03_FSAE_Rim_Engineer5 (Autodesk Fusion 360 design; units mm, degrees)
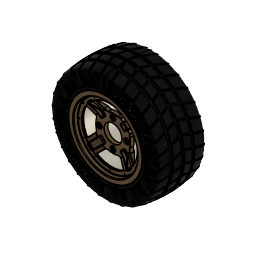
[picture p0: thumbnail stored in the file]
part number: 2026-07-27-09-56-27-671
part number: 2026-08-04-10-59-52-273
part number: 2026-08-04-10-59-52-284
part number: 2026-08-04-10-59-52-289
sketch "Sketch1" plane through (0, 0, 0) normal (1, 0, 0) x axis (0, 1, 0)
  line L1 (153.5, 0) -> (0, 0)
  line L2 (0, 119.5) -> (0, 104)
  line L3 (143.5, 124.5) -> (5, 124.5)
  line L4 (148.5, 134.75) -> (148.5, 129.5)
  line L5 (153.5, 138.25) -> (152, 138.25)
  line L6 (2.5, 119.5) -> (2.5, 104)
  line L7 (143.5, 122) -> (5, 122)
  line L8 (151, 134.75) -> (151, 129.5)
  line L9 (153.5, 135.75) -> (152, 135.75)
  line L10 (2.5, 104) -> (0, 104)
  line L11 (153.5, 135.75) -> (153.5, 138.25)
  arc A1 centre (152, 134.75) radius 3.5 clockwise from (148.5, 134.75) to (152, 138.25)
  arc A2 centre (143.5, 129.5) radius 5 clockwise from (148.5, 129.5) to (143.5, 124.5)
  arc A3 centre (5, 119.5) radius 5 clockwise from (0, 119.5) to (5, 124.5)
  arc A4 centre (5, 119.5) radius 2.5 clockwise from (2.5, 119.5) to (5, 122)
  arc A5 centre (143.5, 129.5) radius 7.5 clockwise from (151, 129.5) to (143.5, 122)
  arc A6 centre (152, 134.75) radius 1 clockwise from (151, 134.75) to (152, 135.75)
  point P1 (0, 0)
  point P2 (0, 0)
  point P4 (0, 104)
  point P3 (153.5, 0)
  point P7 (153.5, 138.25)
  point P6 (148.5, 124.5)
  point P5 (0, 124.5)
  coincident P1 P2
  horizontal L1
  perpendicular L1 L2
  perpendicular L2 L3
  perpendicular L3 L4
  perpendicular L4 L5
  vertical P1 P4
  vertical P3 P7
  tangent L4 A1
  tangent L5 A1
  coincident P6 L3
  coincident P6 L4
  tangent L3 A2
  tangent L4 A2
  coincident P5 L2
  coincident P5 L3
  tangent L2 A3
  tangent L3 A3
  equal A2 A3
  perpendicular L6 L10
  perpendicular L9 L11
  dimension "d1" distance P2 P3 = 153.5
  dimension "d2" = 208
  dimension "d3" = 249
  dimension "d4" = 276.5
  dimension "d5" distance P5 P6 = 148.5
  dimension "d6" radius A1 = 3.5
  dimension "d7" radius A2 = 5
  dimension "d8" = 2.5
revolve "Revolve1" sketch "Sketch1" AlongAngle 360 bodies "FSAE Rim Back"
sketch "Sketch2" plane through (0, 0, 0) normal (0, -1, 0) x axis (1, 0, 0)
  circle C1 centre (0, 0) radius 104
  circle C2 centre (0, 0) radius 119.5
  circle C3 centre (0, 0) radius 112
  circle C4 centre (0, 112) radius 2.15
  point P1 (0, 0)
  point P3 (0, 0)
  point P4 (0, 112)
  coincident P1 P3
  coincident C3 P4
  vertical P3 P4
  dimension "d10" diameter C3 = 224
  dimension "d11" diameter C4 = 4.3
extrude "Extrude1" cut sketch "Sketch2" profile of C4 to an object
circular_pattern "C-Pattern1" TotalAngle 360
canvas "Canvas1"
move "Move1"
sketch "Sketch4" plane through (0, 0, 0) normal (1, 0, 0) x axis (0, 1, 0)
  line L1 (14, 0) -> (0, 0)
  line L2 (14, 72.5) -> (14, 0)
  line L3 (-8, 102.5) -> (14, 72.5)
  line L4 (-8, 124.5) -> (-8, 102.5)
  line L5 (-23.5, 124.5) -> (-8, 124.5)
  line L6 (-23.5, 138) -> (-23.5, 124.5)
  line L7 (-28.25, 138) -> (-23.5, 138)
  line L8 (-28.25, 0) -> (-28.25, 138)
  line L9 (0, 0) -> (-28.25, 0)
  line L10 (-13, 118.1658) -> (-28.25, 119.5)
  line L11 (-13, 102.5) -> (-13, 118.1658)
  line L12 (0, 68.6338) -> (-13, 102.5)
  line L13 (0, 0) -> (0, 68.6338)
  point P1 (0, 0)
  point P2 (0, 0)
  point P11 (0, 0)
  point P12 (-28.25, 119.5)
  point P5 (-8, 102.5)
  point P14 (-13, 102.5)
  point P3 (14, 0)
  point P4 (14, 72.5)
  point P6 (-8, 124.5)
  point P8 (-23.5, 138)
  point P9 (-28.25, 138)
  coincident P1 P2
  horizontal L1
  perpendicular L1 L2
  perpendicular L1 L4
  perpendicular L4 L5
  perpendicular L5 L6
  perpendicular L6 L7
  coincident P1 P11
  collinear L1 L9
  perpendicular L8 L9
  coincident L8 P12
  parallel L8 L11
  vertical L13
  horizontal P5 P14
  dimension "d29" distance P2 P3 = 14
  dimension "d30" = 145
  dimension "d31" = 205
  dimension "d32" = 249
  dimension "d33" = 276
  dimension "d34" distance P4 P6 = 22
  dimension "d35" distance P6 P8 = 15.5
  dimension "d36" distance P8 P9 = 4.75
  dimension "d37" distance L4 L11 = 5
  dimension "d38" angle L12 L13 = 159
  dimension "d39" angle L10 L11 = 95
  dimension "d40" = 239
revolve "Revolve3" sketch "Sketch4" AlongAngle 360 bodies "FSAE Rim Front"
sketch "Sketch5" plane through (0, 0, 0) normal (0, -1, 0) x axis (1, 0, 0)
  circle C1 centre (0, 0) radius 68.6338
  circle C2 centre (0, 0) radius 33
  point P1 (0, 0)
  point P3 (0, 0)
  coincident P1 P3
  dimension "d42" diameter C2 = 66
extrude "Extrude2" cut sketch "Sketch5" profile of C2 to an object
sketch "Sketch6" plane through (0, 0, 0) normal (0, -1, 0) x axis (1, 0, 0)
  circle C1 centre (0, 0) radius 33
  circle C2 centre (0, 0) radius 68.6338
  circle C3 centre (0, 0) radius 50.8
  point P1 (0, 0)
  point P4 (0, 0)
  point P3 (0, 50.8)
  coincident P1 P4
  coincident P3 C3
  vertical P1 P3
  dimension "d45" diameter C3 = 101.6
hole "Hole1" HoleDiameter 10.5 TipAngle 180 CBDepth 5 CBDiameter 20
chamfer "Chamfer2" sketch "Sketch1" distance 0.5
circular_pattern "C-Pattern2" TotalAngle 360
sketch "Sketch7" plane through (0, -13, 0) normal (0, -1, 0) x axis (1, 0, 0)
  circle C1 centre (0, 0) radius 102.5
  circle C2 centre (0, 0) radius 118.1658
  circle C3 centre (0, 0) radius 112
  point P1 (0, 0)
  point P3 (0, 0)
  point P4 (0, 112)
  coincident P1 P3
  coincident C3 P4
  vertical P1 P4
  dimension "d53" diameter C3 = 224
hole "Hole2" HoleDiameter 4.3 TipAngle 180
circular_pattern "C-Pattern3" TotalAngle 360
fillet "Fillet1" radius 1 3 2
chamfer "Chamfer1" distance 0.5
form "Form1" bodies "Tire"
fillet "Fillet2" radius 5
sketch "Sketch8" plane through (0, 0, 0) normal (1, 0, 0) x axis (0, 1, 0)
  line L1 (47.5, 224.911) -> (47.5, 204.911)
  line L2 (57.5, 224.911) -> (47.5, 224.911)
  line L3 (57.5, 204.9943) -> (57.5, 224.911)
  line L4 (87.5, 224.911) -> (87.5, 204.2438)
  line L5 (97.5, 224.911) -> (87.5, 224.911)
  line L6 (97.5, 203.6595) -> (97.5, 224.911)
  line L7 (17.5, 224.911) -> (17.5, 203.6595)
  line L8 (7.5, 224.911) -> (17.5, 224.911)
  line L9 (7.5, 202.9073) -> (7.5, 224.911)
  arc A1 centre (57.5, -395.0057) radius 600 clockwise from (-46, 196) to (161, 196)
  point P2 (-46, 196)
  point P3 (161, 196)
  point P8 (57.5, 204.9943)
  point P9 (87.5, 204.2438)
  point P12 (97.5, 203.6595)
  point P13 (17.5, 203.6595)
  point P16 (7.5, 202.9073)
  point P5 (47.5, 204.911)
  point P1 (0, 0)
  point P6 (47.5, 224.911)
  point P7 (57.5, 224.911)
  horizontal P2 P3
  vertical L1
  perpendicular L1 L2
  midpoint A1 P8
  perpendicular L2 L3
  coincident A1 P9
  parallel L3 L4
  perpendicular L4 L5
  coincident A1 P12
  perpendicular L5 L6
  coincident A1 P13
  perpendicular L5 L7
  perpendicular L7 L8
  coincident A1 P16
  perpendicular L8 L9
  collinear L2 L8
  collinear L2 L5
  equal L2 L8
  equal L2 L5
  coincident A1 P5
  dimension "d68" radius A1 = 600
  dimension "d69" distance P1 P3 = 196
  dimension "d70" distance P1 P2 = 46
  dimension "d71" distance P1 P3 = 161
  dimension "d73" distance P6 P7 = 10
  dimension "d74" distance L1 L7 = 30
  dimension "d75" distance L3 L4 = 30
  dimension "d76" distance P5 P6 = 20
revolve "Revolve4" AlongAngle 360
revolve "Revolve5" sketch "Sketch8" AlongAngle 360
work_plane "WorkPlane1" AlongDistance 275 ExtraOffset 0
sketch "Sketch9" plane through (0, 0, 275) normal (0, 0, 1) x axis (1, 0, 0)
  line L1 (-48.7008, 53.5011) -> (0, -75.7953)
  line L2 (0, 197.5142) -> (-48.7008, 53.5011)
  line L3 (-43.392, 53.5917) -> (4.6791, -74.0329)
  line L4 (4.7365, 195.9124) -> (-43.392, 53.5917)
  line L5 (4.6791, -74.0329) -> (0, -75.7953)
  line L6 (0, 197.5142) -> (4.7365, 195.9124)
  perpendicular L3 L5
  perpendicular L2 L6
  dimension "d80" = 5
step "SurfaceExtend" extendDistance 125
extrude "Extrude3" cut sketch "Sketch9" to an object
circular_pattern "C-Pattern4" countU 30 TotalAngle 360
remove_body "RemoveBody1"
remove_body "RemoveBody2"
work_plane "WorkPlane2" AlongDistance -150 ExtraOffset 0
sketch "Sketch10" plane through (0, -150, 0) normal (0, 1, 0) x axis (1, 0, 0)
  circle C1 centre (0, 0) radius 157.5
  point P1 (0, 0)
  point P2 (0, 0)
  coincident P1 P2
  dimension "d88" diameter C1 = 315
  dimension "d89" Text1-Height = 20
extrude "Extrude4" sketch "Sketch10" blind 2
circular_pattern "C-Pattern5" TotalAngle 360
component_from_bodies "Body->Comp1"
component_from_bodies "Body->Comp2"
component_from_bodies "Body->Comp3"
sketch "Sketch1" plane through (0, -13, 0) normal (0, -1, 0) x axis (1, 0, 0)
  line L1 (0, 103.056) -> (0, 0)
  line L2 (103.056, 0) -> (0, 0)
  line L3 (72.8716, 72.8716) -> (0, 0)
  line L4 (88.3726, 53.0172) -> (60.1041, 24.7487)
  line L5 (53.0172, 88.3726) -> (24.7487, 60.1041)
  circle C1 centre (0, 0) radius 103.056
  circle C2 centre (0, 112) radius 2.15
  circle C3 centre (56, 96.9948) radius 2.15
  circle C4 centre (96.9948, 56) radius 2.15
  circle C5 centre (112, 0) radius 2.15
  circle C6 centre (96.9948, -56) radius 2.15
  circle C7 centre (56, -96.9948) radius 2.15
  circle C8 centre (0, -112) radius 2.15
  circle C9 centre (-56, -96.9948) radius 2.15
  circle C10 centre (-96.9948, -56) radius 2.15
  circle C11 centre (-112, 0) radius 2.15
  circle C12 centre (-96.9948, 56) radius 2.15
  circle C13 centre (-56, 96.9948) radius 2.15
  circle C14 centre (0, 0) radius 116.3331
  arc A1 centre (0, 0) radius 65 clockwise from (0, 65) to (65, 0)
  arc A2 centre (0, 0) radius 65 clockwise from (65, 0) to (0, 65)
  point P2 (0, 0)
  point P16 (0, 0)
  point P17 (0, 103.056)
  point P18 (103.056, 0)
  point P15 (0, 0)
  point P19 (0, 0)
  point P20 (72.8716, 72.8716)
  point P22 (24.7487, 60.1041)
  point P21 (60.1041, 24.7487)
  point P23 (53.0172, 88.3726)
  point P24 (88.3726, 53.0172)
  point P25 (0, 65)
  point P26 (65, 0)
  concentric C1 A1
  coincident P2 P16
  coincident C1 P17
  vertical L1
  coincident C1 P18
  perpendicular L1 L2
  coincident P15 P19
  coincident C1 P20
  coincident P22 A1
  coincident P21 A1
  coincident C1 P23
  coincident C1 P24
  coincident L1 P25
  coincident L2 P26
  concentric A1 A2
  dimension "d95" diameter A1 = 130
  dimension "d96" angle L1 L3 = 45
extrude "Extrude1" cut sketch "Sketch1" profile of C1 L1 L2 L4 L5 A1 to an object
circular_pattern "C-Pattern1" TotalAngle 360
sketch "Sketch2" plane through (0, -13, 0) normal (0, -1, 0) x axis (1, 0, 0)
  line L1 (72.8716, 72.8716) -> (0, 0)
  line L2 (65.9862, 82.9568) -> (25.8367, 42.8073)
  line L3 (82.9568, 65.9862) -> (42.8073, 25.8367)
  arc A1 centre (0, 0) radius 103.056 clockwise from (-53.0172, 88.3726) to (53.0172, 88.3726)
  arc A2 centre (0, 0) radius 103.056 clockwise from (53.0172, 88.3726) to (88.3726, 53.0172)
  arc A3 centre (0, 0) radius 103.056 clockwise from (88.3726, 53.0172) to (88.3726, -53.0172)
  arc A4 centre (0, 0) radius 103.056 clockwise from (88.3726, -53.0172) to (53.0172, -88.3726)
  arc A5 centre (0, 0) radius 103.056 clockwise from (53.0172, -88.3726) to (-53.0172, -88.3726)
  arc A6 centre (0, 0) radius 103.056 clockwise from (-53.0172, -88.3726) to (-88.3726, -53.0172)
  arc A7 centre (0, 0) radius 103.056 clockwise from (-88.3726, -53.0172) to (-88.3726, 53.0172)
  arc A8 centre (0, 0) radius 103.056 clockwise from (-88.3726, 53.0172) to (-53.0172, 88.3726)
  circle C1 centre (0, 112) radius 2.15
  circle C2 centre (56, 96.9948) radius 2.15
  circle C3 centre (96.9948, 56) radius 2.15
  circle C4 centre (112, 0) radius 2.15
  circle C5 centre (96.9948, -56) radius 2.15
  circle C6 centre (56, -96.9948) radius 2.15
  circle C7 centre (0, -112) radius 2.15
  circle C8 centre (-56, -96.9948) radius 2.15
  circle C9 centre (-96.9948, -56) radius 2.15
  circle C10 centre (-112, 0) radius 2.15
  circle C11 centre (-96.9948, 56) radius 2.15
  circle C12 centre (-56, 96.9948) radius 2.15
  circle C13 centre (0, 0) radius 116.3331
  circle C14 centre (0, 0) radius 50
  circle C15 centre (0, 0) radius 106
  point P23 (0, 0)
  point P25 (0, 0)
  point P27 (25.8367, 42.8073)
  point P28 (42.8073, 25.8367)
  point P29 (82.9568, 65.9862)
  point P30 (65.9862, 82.9568)
  parallel L1 L2
  parallel L1 L3
  coincident P23 P25
  concentric C14 C15
  coincident C14 P27
  coincident C14 P28
  coincident C15 P29
  coincident C15 P30
  dimension "d103" distance L1 L2 = 12
  dimension "d104" distance L1 L3 = 12 (= "d103")
  dimension "d105" diameter C14 = 100
  dimension "d106" diameter C15 = 212
extrude "Extrude2" cut sketch "Sketch2" profile of A2 L2 L3 C14 C15 to an object offset 2
fillet "Fillet1" radius 5
fillet "Fillet2" radius 10
fillet "Fillet3" radius 2
circular_pattern "C-Pattern2" TotalAngle 360
fillet "Fillet4" radius 15 5
chamfer "Chamfer1" sketch "Sketch1" distance 1
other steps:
base_feature "Base Feature1" bodies "FSAE Rim Back"
base_feature "Base Feature1" bodies "Tire"
base_feature "Base Feature1" bodies "FSAE Rim Front"
create_component "CreateComponent1"
reparent_decal "ReparentDecal1"
remove_body "RemoveBody3"
create_component "CreateComponent2"
reparent_decal "ReparentDecal2"
remove_body "RemoveBody4"
create_component "CreateComponent3"
reparent_decal "ReparentDecal3"
remove_body "RemoveBody5"
named bodies: "FSAE Rim Back", "FSAE Rim Front", "Tire"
